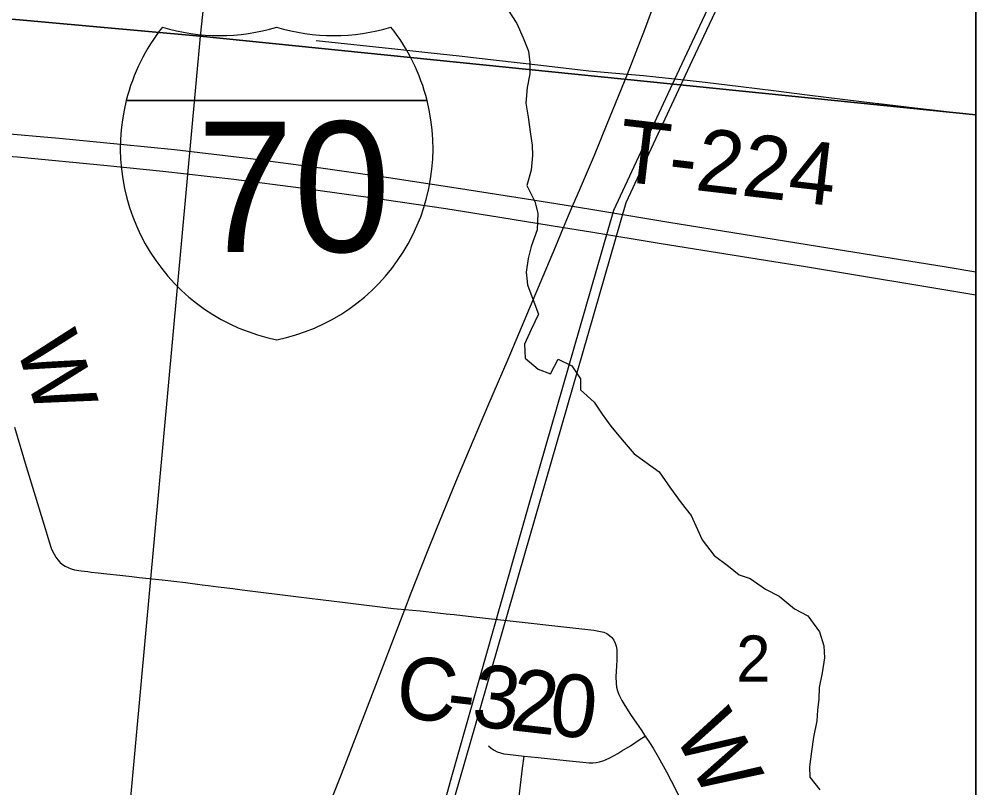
# Model space of a CAD drawing. Extents: x 0 to 1134, y 0 to 440.
# Drawn here: x 512.92 to 539, y 155.8 to 176.75 of the extents above; entities that cross this region are included whole.
import ezdxf

# ---------------------------------------------------------------- set-up
doc = ezdxf.new("R2010")
doc.units = 0
for name, color, linetype in [('Default', 7, 'Continuous'), ('GM_X_County_Road', 7, 'Continuous'), ('GM_X_County_Road_Text', 7, 'Continuous'), ('GM_X_Interstate_Location', 7, 'Continuous'), ('GM_X_Interstate_Route', 7, 'Continuous'), ('GM_X_Interstate_Shield', 7, 'Continuous'), ('GM_X_Minor_River', 7, 'Continuous'), ('GM_X_Rail_Line', 7, 'Continuous'), ('GM_X_Section', 7, 'Continuous'), ('GM_X_Section_Text', 7, 'Continuous'), ('GM_X_Township_Road', 7, 'Continuous'), ('GM_X_Township_Road_Text', 7, 'Continuous'), ('GM_X_Unincorporated', 7, 'Continuous'), ('SH_Cut_Line', 7, 'Continuous'), ('SH_Text', 7, 'Continuous')]:
    doc.layers.add(name, color=color, linetype=linetype)

msp = doc.modelspace()

# ---------------------------------------------------------------- linework, layer by layer
at = {"layer": 'Default'}
for points in [[(539, 174.139), (539, 205.4), (521.182, 207.228), (517.859, 176.283)], [(539, 143.681), (539, 174.139), (517.859, 176.283), (515.105, 146.205)]]:
    msp.add_lwpolyline(points, close=True, dxfattribs=at)
at = {"layer": 'GM_X_County_Road'}
for points in [[(529.505, 175.252), (529.739, 175.858), (529.974, 176.467), (530.685, 178.393), (530.895, 178.971)], [(526.762, 168.694), (527.553, 170.566), (527.763, 171.075), (527.894, 171.394), (528.005, 171.649), (528.224, 172.149), (528.609, 173.046), (528.949, 173.9), (529.505, 175.252)], [(523.436, 160.658), (523.612, 161.117), (524.057, 162.243), (524.297, 162.849), (524.827, 164.142), (525.694, 166.202), (526.251, 167.483), (526.762, 168.694)], [(518.225, 147.183), (518.307, 147.392), (519.314, 149.998), (519.952, 151.649), (520.388, 152.779), (520.796, 153.819), (521.195, 154.863), (521.806, 156.424), (522.646, 158.596), (523.436, 160.658)], [(523.436, 160.658), (523.851, 160.619), (524.338, 160.567), (524.559, 160.543), (524.785, 160.519), (525.159, 160.478), (525.715, 160.418), (526.311, 160.353), (527.933, 160.168), (528.589, 160.093), (528.77, 160.063), (528.857, 160.038), (528.938, 160.002), (529.011, 159.954), (529.076, 159.893), (529.129, 159.823), (529.169, 159.744), (529.196, 159.66), (529.21, 159.571), (529.213, 159.481), (529.213, 159.297), (529.202, 159.112), (529.191, 158.831), (529.198, 158.642), (529.209, 158.547), (529.234, 158.445), (529.27, 158.344), (529.35, 158.183), (529.431, 158.043), (529.591, 157.798), (529.749, 157.565), (529.875, 157.381), (529.986, 157.209)], [(529.986, 157.209), (530.108, 157.037), (530.203, 156.881), (530.345, 156.645), (530.568, 156.238), (530.824, 155.741), (530.983, 155.405), (531.085, 155.147), (531.137, 154.971), (531.154, 154.881), (531.175, 154.699), (531.177, 154.515), (531.161, 154.237), (531.114, 153.692)]]:
    msp.add_lwpolyline(points, dxfattribs=at)
at = {"layer": 'GM_X_Interstate_Route'}
msp.add_line((534.356, 170.004), (539, 169.237), dxfattribs=at)
for points in [[(512.347, 173.649), (514.018, 173.508), (515.688, 173.347), (517.156, 173.196), (519.231, 172.956), (521.146, 172.695), (522.991, 172.437), (524.833, 172.152), (526.754, 171.851), (528.005, 171.649), (528.724, 171.533), (530.627, 171.22), (534.683, 170.563), (538.187, 169.995), (539, 169.862)], [(510.578, 173.166), (511.626, 173.088), (512.875, 172.998), (515.325, 172.758), (516.838, 172.608), (518.778, 172.385), (520.598, 172.151), (522.441, 171.899), (524.555, 171.587), (526.027, 171.353), (527.763, 171.075), (528.507, 170.956), (530.423, 170.638), (533.497, 170.146), (534.356, 170.004)]]:
    msp.add_lwpolyline(points, dxfattribs=at)
at = {"layer": 'GM_X_Interstate_Shield'}
for p, q in [((515.844, 174.536), (524.042, 174.536)), ((524.042, 174.536), (515.844, 174.536)), ((524.042, 174.536), (515.844, 174.536))]:
    msp.add_line(p, q, dxfattribs=at)
for centre, start, end in [((521.008, 173.229), 141.669, 165.8066), ((518.386, 181.627), 253.0091, 286.9909), ((521.499, 181.627), 253.0091, 286.9909), ((518.878, 173.229), 14.1934, 38.331), ((521.008, 173.229), 165.8066, 258.463), ((518.878, 173.229), 281.537, 14.1934)]:
    msp.add_arc(centre, 5.327, start, end, dxfattribs=at)
at = {"layer": 'GM_X_Minor_River'}
for points in [[(526.232, 177.02), (526.491, 176.632), (526.658, 176.244), (526.803, 175.879), (526.846, 175.571), (526.843, 175.264), (526.773, 174.889), (526.735, 174.458), (526.801, 174.082), (526.865, 173.615), (526.908, 173.319), (526.918, 173.034), (526.881, 172.637), (526.764, 172.217), (526.976, 171.783), (527.065, 171.464), (527.039, 171.009), (526.876, 170.555), (526.794, 170.226), (526.746, 169.851), (526.778, 169.51)], [(526.778, 169.51), (526.922, 169.122), (527.078, 168.711), (526.882, 168.292), (526.698, 167.895), (526.717, 167.508), (527.067, 167.21), (527.406, 167.082), (527.614, 167.479), (527.987, 167.305), (528.223, 166.951), (528.22, 166.644), (528.592, 166.311), (528.817, 165.98), (529.053, 165.66), (529.356, 165.282), (529.683, 164.904), (529.976, 164.697), (530.371, 164.41), (530.674, 163.964), (530.966, 163.564), (531.236, 163.221), (531.415, 162.844), (531.538, 162.559), (531.863, 162.135), (532.258, 161.837), (532.552, 161.607), (532.846, 161.502), (533.264, 161.215), (533.637, 161.019), (534.054, 160.675), (534.416, 160.49), (534.742, 160.055), (534.852, 159.668), (534.873, 159.338), (534.813, 158.929), (534.73, 158.531), (534.717, 158.213), (534.68, 157.917), (534.667, 157.622), (534.573, 157.179), (534.524, 156.792), (534.465, 156.372), (534.474, 156.088), (534.744, 155.744)]]:
    msp.add_lwpolyline(points, dxfattribs=at)
at = {"layer": 'GM_X_Rail_Line'}
for points in [[(523.793, 152.748), (524.72, 156.111), (526.82, 163.501), (529.132, 171.547), (530.926, 175.384), (532.671, 179.109), (534.549, 183.03), (536.181, 186.563), (539, 192.493)], [(538.46, 190.872), (531.264, 175.625), (529.455, 171.744), (523.761, 151.987), (521.638, 146.912), (519.773, 143.896), (517.683, 141.431), (515.36, 138.979), (514.776, 138.349), (513.736, 135.72), (513.018, 133.756), (510.064, 126.441), (504.279, 111.389), (503.424, 109.358), (496.783, 96.163), (485.546, 73.661), (478.157, 58.904), (470.789, 44.152), (463.212, 28.991)]]:
    msp.add_lwpolyline(points, dxfattribs=at)
at = {"layer": 'GM_X_Section'}
for points in [[(490.882, 209.496), (521.182, 207.228), (517.859, 176.283), (488.076, 178.987)], [(488.076, 178.987), (517.859, 176.283), (515.105, 146.205), (485.322, 148.876)]]:
    msp.add_lwpolyline(points, close=True, dxfattribs=at)
at = {"layer": 'GM_X_Township_Road'}
for points in [[(521.021, 176.166), (523.241, 175.928), (523.985, 175.846), (524.915, 175.747), (525.938, 175.632), (527.147, 175.497), (528.449, 175.344), (529.189, 175.277), (529.505, 175.252)], [(529.505, 175.252), (529.944, 175.216), (530.28, 175.178), (531.129, 175.086), (531.624, 175.03), (532.592, 174.912), (533.484, 174.802), (534.404, 174.689), (536.325, 174.454), (536.355, 174.45)], [(536.355, 174.45), (537.34, 174.33), (537.895, 174.268), (538.912, 174.153), (539, 174.144)], [(512.795, 165.63), (513.119, 164.558), (513.359, 163.754), (513.524, 163.22), (513.636, 162.864), (513.74, 162.507), (513.8, 162.332), (513.835, 162.247), (513.875, 162.165), (513.921, 162.087), (513.974, 162.014), (514.035, 161.948), (514.106, 161.89), (514.178, 161.841), (514.259, 161.8), (514.343, 161.769), (514.431, 161.744), (514.611, 161.712), (514.796, 161.692), (514.889, 161.681), (515.076, 161.66), (515.311, 161.634), (515.67, 161.595), (515.994, 161.559), (516.196, 161.536), (516.82, 161.467), (517.461, 161.392), (517.912, 161.334), (518.078, 161.313), (518.344, 161.279), (518.752, 161.228), (519.004, 161.197), (520.536, 161.004), (521.739, 160.857), (523.129, 160.689), (523.436, 160.658)], [(526.689, 156.663), (527.072, 156.627), (527.832, 156.542), (528.197, 156.503), (528.29, 156.495), (528.463, 156.476), (528.56, 156.48), (528.653, 156.49), (528.743, 156.505), (528.858, 156.541), (529.009, 156.605), (529.145, 156.681), (529.239, 156.735), (529.346, 156.803), (529.584, 156.947), (529.849, 157.126), (529.986, 157.209)], [(525.719, 156.941), (525.793, 156.882), (525.871, 156.828), (525.955, 156.784), (526.044, 156.752), (526.136, 156.73), (526.23, 156.714), (526.689, 156.663)], [(526.516, 155.256), (526.645, 156.337), (526.689, 156.663)]]:
    msp.add_lwpolyline(points, dxfattribs=at)
at = {"layer": 'GM_X_Unincorporated'}
msp.add_lwpolyline([(539, 113.439), (539, 295.833)], dxfattribs=at)
at = {"layer": 'SH_Cut_Line'}
msp.add_lwpolyline([(539, 17.107), (539, 425.107), (205.806, 425.107)], dxfattribs=at)
at = {"layer": 'SH_Text'}
msp.add_lwpolyline([(131, 425.107), (539, 425.107), (539, 17.107), (131, 17.107)], close=True, dxfattribs=at)

# ---------------------------------------------------------------- texts
at = {"layer": 'GM_X_County_Road_Text'}
for s, rotation, p in [('C', 353.2913, (523.131, 157.743)), ('3', 353.3432, (525.218, 157.498)), ('2', 353.4658, (526.265, 157.376)), ('0', 353.8878, (527.322, 157.255)), ('-', 353.3006, (524.522, 157.58)), ('W', 297.3396, (530.743, 157.31))]:
    msp.add_text(s, height=1.705, rotation=rotation, dxfattribs=at).set_placement(p)
at = {"layer": 'GM_X_Interstate_Location'}
for s in ['-', '.', ',']:
    msp.add_text(s, height=0.00568, dxfattribs=at).set_placement((519.942, 172.269))
msp.add_text('70', height=0.00568, rotation=0, dxfattribs=at).set_placement((518.781, 171.093))
at = {"layer": 'GM_X_Interstate_Shield'}
msp.add_text('70', height=3.5511, dxfattribs=at).set_placement((517.761, 170.407))
at = {"layer": 'GM_X_Section_Text'}
msp.add_text('2', height=1.256, rotation=0, dxfattribs=at).set_placement((532.469, 158.695))
at = {"layer": 'GM_X_Township_Road_Text'}
for s, height, rotation, p in [('T-224', 1.7045, 353.3237, (529.182, 172.346)), ('W', 1.705, 287.5243, (512.821, 167.886))]:
    msp.add_text(s, height=height, rotation=rotation, dxfattribs=at).set_placement(p)

doc.saveas('drawing.dxf')
